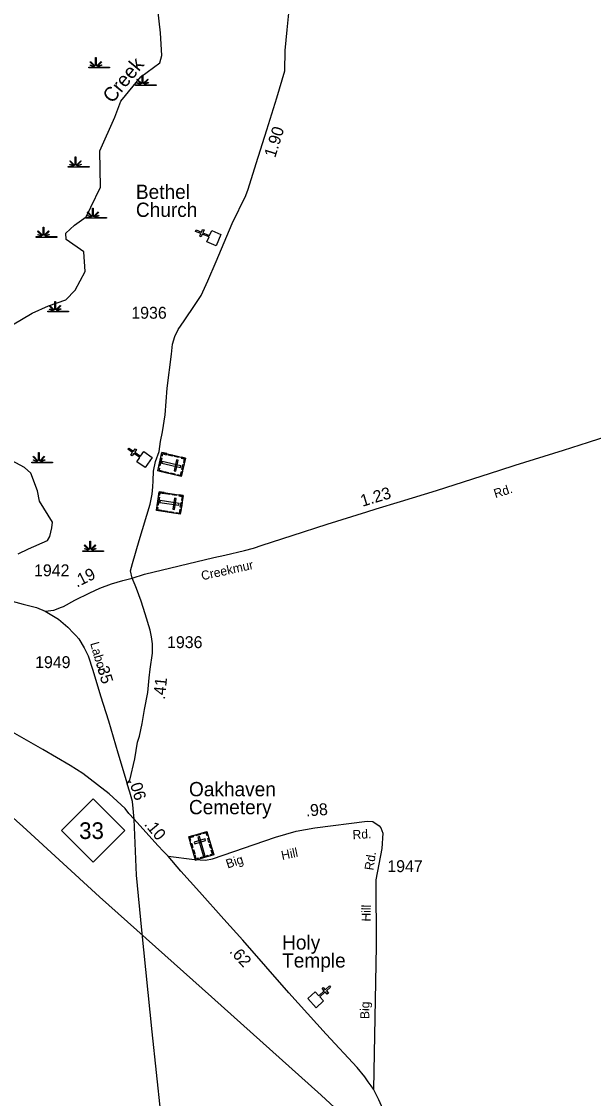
# Model space of a CAD drawing. Extents: x 2532689 to 2764727, y 536648 to 732970.
# Drawn here: x 2635202 to 2641218, y 574044 to 585362 of the extents above; entities that cross this region are included whole.
import ezdxf

# ---------------------------------------------------------------- set-up
doc = ezdxf.new("R2010")
doc.units = 0
for name, color, linetype in [('Exist Cultural Cemetery CELL', 7, 'Continuous'), ('Exist Cultural Cemetery Label', 7, 'Continuous'), ('Exist Cultural Church CELL', 7, 'Continuous'), ('Exist Cultural Church Label', 7, 'Continuous'), ('Exist Hydrographic Creek Single Shore', 7, 'Continuous'), ('Exist Hydrographic Creek Single Shore Label', 7, 'Continuous'), ('Exist Hydrographic Swamp CELL', 7, 'Continuous'), ('Exist Railroad Mainline', 7, 'Continuous'), ('Exist Road Primary Interstate Shield CELL', 7, 'Continuous'), ('Exist Road Primary NC Attributed', 7, 'Continuous'), ('Exist Road Primary NC Mileage Hundredths English Label', 7, 'Continuous'), ('Exist Road Primary NC Shield CELL', 7, 'Continuous'), ('Exist Road Primary NC Shield Number Label', 7, 'Continuous'), ('Exist Road Secondary Mileage Hundredths English Label', 7, 'Continuous'), ('Exist Road Secondary Type 20 Attributed', 7, 'Continuous'), ('Exist Road Secondary Type 51 Attributed', 7, 'Continuous'), ('Exist Road Secondary Type 51 Label', 7, 'Continuous'), ('Exist Road Secondary Type 51 Number Label', 7, 'Continuous')]:
    doc.layers.add(name, color=color, linetype=linetype)

# ---------------------------------------------------------------- blocks, each defined once
blk = doc.blocks.new('Exist Cultural Church')
at = {"layer": 'Exist Road Primary Interstate Shield CELL'}
blk.add_lwpolyline([(-65, 27), (-8, 27), (-8, 103), (-40, 103), (-40, 119), (-8, 119), (-8, 179), (8, 179), (8, 119), (40, 119), (40, 103), (8, 103), (8, 27), (65, 27), (65, -80), (-65, -80)], close=True, dxfattribs=at)

msp = doc.modelspace()

# ---------------------------------------------------------------- linework, layer by layer
at = {"layer": 'Exist Cultural Cemetery CELL'}
for points in [[(2636927, 580775), (2636882, 580581), (2636634, 580639), (2636679, 580833)], [(2636677, 580774), (2636658, 580692), (2636647, 580694), (2636666, 580777)], [(2636671, 580801), (2636683, 580798), (2636688, 580819), (2636727, 580810), (2636730, 580821), (2636679, 580833)], [(2636874, 580676), (2636878, 580694), (2636680, 580740), (2636676, 580722)], [(2636747, 580817), (2636789, 580807), (2636787, 580796), (2636744, 580806)], [(2636851, 580751), (2636833, 580755), (2636807, 580640), (2636825, 580636)], [(2636813, 580802), (2636855, 580792), (2636852, 580781), (2636810, 580791)], [(2636885, 580785), (2636882, 580774), (2636914, 580767), (2636904, 580727), (2636915, 580725), (2636927, 580775)], [(2636641, 580671), (2636653, 580669), (2636648, 580647), (2636687, 580638), (2636684, 580627), (2636634, 580639)], [(2636707, 580634), (2636749, 580624), (2636746, 580613), (2636704, 580623)], [(2636840, 580591), (2636842, 580602), (2636874, 580595), (2636883, 580634), (2636894, 580632), (2636882, 580581)], [(2636910, 580703), (2636898, 580653), (2636887, 580655), (2636899, 580706)], [(2636771, 580619), (2636813, 580609), (2636811, 580598), (2636768, 580608)], [(2636903, 580381), (2636872, 580184), (2636620, 580224), (2636651, 580421)], [(2636646, 580388), (2636657, 580386), (2636661, 580408), (2636701, 580402), (2636702, 580413), (2636651, 580421)], [(2636720, 580410), (2636763, 580403), (2636761, 580392), (2636718, 580398)], [(2636787, 580399), (2636829, 580392), (2636828, 580381), (2636785, 580388)], [(2636654, 580362), (2636640, 580278), (2636629, 580280), (2636642, 580364)], [(2636857, 580278), (2636860, 580296), (2636659, 580328), (2636656, 580309)], [(2636829, 580351), (2636811, 580354), (2636792, 580238), (2636811, 580235)], [(2636860, 580388), (2636858, 580376), (2636890, 580371), (2636884, 580331), (2636895, 580329), (2636903, 580381)], [(2636891, 580308), (2636883, 580256), (2636872, 580258), (2636880, 580309)], [(2636625, 580257), (2636637, 580255), (2636633, 580233), (2636673, 580227), (2636671, 580216), (2636620, 580224)], [(2636693, 580224), (2636736, 580217), (2636734, 580206), (2636691, 580213)], [(2636758, 580214), (2636801, 580207), (2636799, 580196), (2636756, 580202)], [(2636829, 580191), (2636830, 580202), (2636862, 580197), (2636869, 580237), (2636880, 580235), (2636871, 580184)], [(2636960, 576793), (2637151, 576850), (2637224, 576605), (2637033, 576549)], [(2636973, 576751), (2636983, 576754), (2636974, 576785), (2637013, 576797), (2637010, 576808), (2636960, 576793)], [(2637031, 576814), (2637081, 576829), (2637084, 576818), (2637034, 576803)], [(2637073, 576796), (2637055, 576790), (2637113, 576596), (2637131, 576601)], [(2637163, 576808), (2637153, 576805), (2637143, 576836), (2637105, 576824), (2637101, 576835), (2637151, 576849)], [(2637173, 576735), (2637161, 576776), (2637172, 576779), (2637184, 576738)], [(2636994, 576680), (2636981, 576722), (2636992, 576725), (2637005, 576683)], [(2637019, 576739), (2637024, 576721), (2637137, 576755), (2637132, 576773)], [(2637192, 576671), (2637180, 576713), (2637191, 576716), (2637203, 576675)], [(2637013, 576616), (2637000, 576657), (2637011, 576660), (2637024, 576619)], [(2637065, 576558), (2637061, 576569), (2637040, 576563), (2637029, 576602), (2637018, 576598), (2637033, 576549)], [(2637085, 576576), (2637166, 576600), (2637169, 576589), (2637088, 576565)], [(2637192, 576596), (2637189, 576607), (2637210, 576613), (2637198, 576652), (2637209, 576655), (2637224, 576605)]]:
    msp.add_lwpolyline(points, close=True, dxfattribs=at)
at = {"layer": 'Exist Cultural Church CELL'}
for points in [[(2637151, 583046), (2637174, 583098), (2637103, 583128), (2637091, 583098), (2637076, 583105), (2637089, 583134), (2637033, 583157), (2637040, 583172), (2637095, 583149), (2637107, 583178), (2637122, 583172), (2637110, 583143), (2637180, 583113), (2637202, 583166), (2637300, 583124), (2637250, 583004)], [(2636414, 580734), (2636446, 580781), (2636383, 580824), (2636365, 580797), (2636352, 580806), (2636370, 580833), (2636320, 580867), (2636329, 580880), (2636379, 580846), (2636397, 580873), (2636410, 580864), (2636392, 580837), (2636455, 580795), (2636487, 580842), (2636576, 580782), (2636502, 580674)]]:
    msp.add_lwpolyline(points, close=True, dxfattribs=at)
at = {"layer": 'Exist Hydrographic Creek Single Shore'}
for points in [[(2635671, 583072), (2635669, 583137), (2635759, 583223), (2635882, 583310), (2635930, 583411), (2636033, 583622), (2636025, 584005), (2636184, 584357), (2636247, 584527), (2636458, 584781), (2636655, 584927), (2636678, 585004), (2636664, 585243), (2636613, 585677)], [(2635107, 582176), (2635313, 582296), (2635486, 582375), (2635668, 582438), (2635766, 582540), (2635870, 582735), (2635857, 582941), (2635671, 583072)], [(2635168, 579768), (2635276, 579822), (2635474, 579909), (2635498, 579949), (2635521, 580042), (2635528, 580101), (2635390, 580322), (2635371, 580430), (2635300, 580614), (2635232, 580677), (2634962, 580820)]]:
    msp.add_lwpolyline(points, dxfattribs=at)
at = {"layer": 'Exist Hydrographic Swamp CELL'}
for points in [[(2635909, 584882), (2635962, 584882), (2635964, 584886), (2635926, 584901), (2635928, 584906), (2635966, 584890), (2635968, 584893), (2635923, 584937), (2635928, 584943), (2635974, 584897), (2635980, 584899), (2635980, 584983), (2635987, 584983), (2635987, 584899), (2635994, 584897), (2636039, 584943), (2636044, 584937), (2636000, 584893), (2636002, 584889), (2636043, 584908), (2636045, 584903), (2636004, 584885), (2636006, 584882), (2636127, 584882), (2636127, 584875), (2635909, 584875)], [(2636400, 584698), (2636453, 584698), (2636455, 584702), (2636416, 584716), (2636419, 584722), (2636457, 584706), (2636459, 584709), (2636414, 584753), (2636419, 584758), (2636465, 584713), (2636471, 584715), (2636471, 584798), (2636478, 584798), (2636478, 584715), (2636484, 584713), (2636530, 584758), (2636535, 584753), (2636491, 584709), (2636493, 584705), (2636533, 584724), (2636536, 584719), (2636495, 584701), (2636496, 584698), (2636618, 584698), (2636618, 584691), (2636400, 584691)], [(2635694, 583838), (2635747, 583838), (2635749, 583842), (2635711, 583857), (2635714, 583862), (2635751, 583846), (2635753, 583849), (2635709, 583894), (2635714, 583899), (2635759, 583853), (2635765, 583856), (2635765, 583939), (2635773, 583939), (2635773, 583856), (2635779, 583853), (2635824, 583899), (2635829, 583894), (2635785, 583849), (2635787, 583846), (2635828, 583864), (2635830, 583859), (2635789, 583841), (2635791, 583838), (2635912, 583838), (2635912, 583831), (2635694, 583831)], [(2635878, 583301), (2635931, 583301), (2635933, 583305), (2635895, 583320), (2635898, 583325), (2635935, 583309), (2635937, 583312), (2635893, 583356), (2635898, 583362), (2635943, 583316), (2635949, 583318), (2635949, 583402), (2635957, 583402), (2635957, 583318), (2635963, 583316), (2636008, 583362), (2636013, 583356), (2635969, 583312), (2635971, 583308), (2636012, 583327), (2636014, 583322), (2635973, 583304), (2635975, 583301), (2636096, 583301), (2636096, 583294), (2635878, 583294)], [(2635357, 583102), (2635410, 583102), (2635412, 583105), (2635373, 583120), (2635376, 583125), (2635414, 583109), (2635416, 583112), (2635371, 583157), (2635376, 583162), (2635422, 583117), (2635428, 583119), (2635428, 583202), (2635435, 583202), (2635435, 583119), (2635441, 583117), (2635487, 583162), (2635492, 583157), (2635447, 583112), (2635449, 583109), (2635490, 583127), (2635493, 583122), (2635452, 583105), (2635453, 583102), (2635574, 583102), (2635574, 583094), (2635357, 583094)], [(2635480, 582319), (2635532, 582319), (2635534, 582322), (2635496, 582337), (2635499, 582342), (2635537, 582327), (2635538, 582330), (2635494, 582374), (2635499, 582379), (2635544, 582334), (2635551, 582336), (2635551, 582419), (2635558, 582419), (2635558, 582336), (2635564, 582334), (2635609, 582379), (2635615, 582374), (2635570, 582330), (2635572, 582326), (2635613, 582345), (2635615, 582340), (2635574, 582322), (2635576, 582319), (2635697, 582319), (2635697, 582312), (2635480, 582312)], [(2635310, 580732), (2635363, 580733), (2635365, 580736), (2635326, 580751), (2635329, 580756), (2635367, 580740), (2635369, 580743), (2635324, 580788), (2635329, 580793), (2635375, 580747), (2635381, 580750), (2635381, 580833), (2635388, 580833), (2635388, 580750), (2635395, 580747), (2635440, 580793), (2635445, 580788), (2635401, 580743), (2635403, 580740), (2635443, 580758), (2635446, 580753), (2635405, 580735), (2635407, 580733), (2635528, 580732), (2635528, 580725), (2635310, 580725)], [(2635848, 579801), (2635900, 579801), (2635902, 579805), (2635864, 579820), (2635867, 579825), (2635905, 579809), (2635906, 579812), (2635862, 579857), (2635867, 579862), (2635912, 579816), (2635919, 579819), (2635919, 579902), (2635926, 579902), (2635926, 579819), (2635932, 579816), (2635978, 579862), (2635983, 579857), (2635938, 579812), (2635940, 579809), (2635981, 579827), (2635984, 579822), (2635943, 579804), (2635944, 579801), (2636065, 579801), (2636065, 579794), (2635848, 579794)]]:
    msp.add_lwpolyline(points, close=True, dxfattribs=at)
at = {"layer": 'Exist Railroad Mainline'}
msp.add_lwpolyline([(2623480, 582454), (2630987, 579432), (2631132, 579385), (2631273, 579334), (2631408, 579295), (2631458, 579280), (2633928, 578052), (2635217, 576901), (2636021, 576162), (2637199, 575112), (2638354, 574078), (2639181, 573315), (2639635, 572920), (2639933, 572574), (2640299, 572140), (2640552, 571834), (2640858, 571472), (2641178, 571089), (2641375, 570864)], dxfattribs=at)
at = {"layer": 'Exist Road Primary NC Attributed'}
for points in [[(2636385, 576981), (2636332, 577040), (2636292, 577091), (2636123, 577245), (2636002, 577340), (2635845, 577459), (2635712, 577543), (2635427, 577712), (2635084, 577907), (2634767, 578089)], [(2636746, 576590), (2636694, 576638), (2636637, 576704), (2636385, 576981)], [(2638906, 574142), (2638879, 574177), (2638848, 574220), (2638813, 574271), (2638733, 574368), (2638408, 574721), (2638014, 575154), (2637530, 575708), (2637330, 575928), (2637074, 576215), (2636877, 576433), (2636746, 576590)], [(2640314, 569721), (2640238, 569792), (2640156, 569865), (2640060, 569996), (2639996, 570116), (2639957, 570244), (2639932, 570350), (2639841, 570684), (2639635, 571493), (2639475, 572118), (2639462, 572170), (2639449, 572221), (2639432, 572279), (2639414, 572337), (2639385, 572480), (2639272, 572901), (2639058, 573761), (2639003, 573935), (2638962, 574030), (2638906, 574142)]]:
    msp.add_lwpolyline(points, dxfattribs=at)
at = {"layer": 'Exist Road Primary NC Shield CELL'}
msp.add_lwpolyline([(2635621, 576861), (2635954, 577194), (2636287, 576861), (2635954, 576528)], close=True, dxfattribs=at)
at = {"layer": 'Exist Road Secondary Type 20 Attributed'}
msp.add_lwpolyline([(2636365, 579512), (2636494, 579553), (2637226, 579728), (2637340, 579754), (2637547, 579804), (2637642, 579828), (2637733, 579858), (2638050, 579959), (2638417, 580078), (2638833, 580209), (2638933, 580240), (2639188, 580317), (2639567, 580435), (2640233, 580648), (2640395, 580700), (2640699, 580793), (2640904, 580858), (2641165, 580940), (2641395, 581014)], dxfattribs=at)
at = {"layer": 'Exist Road Secondary Type 51 Attributed'}
for points in [[(2636365, 579512), (2636347, 579588), (2636368, 579666), (2636441, 579907), (2636556, 580291), (2636575, 580396), (2636582, 580472), (2636585, 580534), (2636590, 580636), (2636610, 580740), (2636648, 580843), (2636665, 580949), (2636684, 581051), (2636712, 581230), (2636734, 581510), (2636779, 581868), (2636791, 581970), (2636814, 582052), (2636848, 582126), (2636914, 582217), (2637028, 582390), (2637092, 582484), (2637161, 582636), (2637251, 582839), (2637417, 583239), (2637562, 583534), (2637587, 583602), (2637671, 583872), (2637781, 584225), (2637886, 584559), (2637970, 584845), (2637976, 585057), (2637996, 585276), (2638016, 585484)], [(2634156, 579541), (2634265, 579490), (2634419, 579427), (2634592, 579377), (2634855, 579321), (2635050, 579283), (2635218, 579239), (2635360, 579204), (2635452, 579166)], [(2635452, 579166), (2635542, 579177), (2635623, 579206), (2635642, 579215), (2635761, 579280), (2635922, 579359), (2636027, 579406), (2636148, 579452), (2636268, 579489), (2636365, 579512)], [(2636313, 577349), (2636340, 577390), (2636393, 577614), (2636423, 577788), (2636444, 577850), (2636471, 577984), (2636494, 578131), (2636530, 578310), (2636545, 578466), (2636556, 578556), (2636579, 578723), (2636581, 578823), (2636570, 578897), (2636555, 578965), (2636501, 579138), (2636460, 579271), (2636412, 579404), (2636396, 579439), (2636365, 579512)], [(2635452, 579166), (2635589, 579081), (2635690, 578998), (2635750, 578933), (2635774, 578909), (2635805, 578876), (2635862, 578781), (2635902, 578697), (2635952, 578545), (2636034, 578275), (2636116, 578013), (2636214, 577675), (2636313, 577349)], [(2636385, 576981), (2636368, 577165), (2636340, 577264), (2636313, 577349)], [(2636667, 573888), (2636576, 574744), (2636469, 575812), (2636412, 576391), (2636385, 576981)], [(2636746, 576590), (2637023, 576554), (2637136, 576550), (2637211, 576563), (2637872, 576790), (2638090, 576853), (2638288, 576889), (2638837, 576957), (2638899, 576955), (2638963, 576910), (2638983, 576887)], [(2638983, 576887), (2639004, 576832), (2638993, 576672), (2638928, 576343), (2638931, 575644), (2638906, 574142)]]:
    msp.add_lwpolyline(points, dxfattribs=at)

# ---------------------------------------------------------------- block references
at = {"layer": 'Exist Cultural Church CELL', "rotation": -47.63063884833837}
msp.add_blockref('Exist Cultural Church', (2638315, 575100), dxfattribs=at)

# ---------------------------------------------------------------- texts
at = {"layer": 'Exist Cultural Cemetery Label'}
for s, p in [('Oakhaven', (2636963, 577220)), ('Cemetery', (2636963, 577031))]:
    msp.add_text(s, height=150, dxfattribs=at).set_placement(p)
at = {"layer": 'Exist Cultural Church Label'}
for s, p in [('Bethel', (2636405, 583498)), ('Church', (2636405, 583309)), ('Holy', (2637943, 575609)), ('Temple', (2637943, 575420))]:
    msp.add_text(s, height=150, dxfattribs=at).set_placement(p)
at = {"layer": 'Exist Hydrographic Creek Single Shore Label'}
msp.add_text('Creek', height=150, rotation=50.3695, dxfattribs=at).set_placement((2636157, 584495))
at = {"layer": 'Exist Road Primary NC Mileage Hundredths English Label'}
for s, rotation, p in [('.10', 309.8557, (2636486, 576923)), ('.62', 312.5985, (2637382, 575584))]:
    msp.add_text(s, height=125, rotation=rotation, dxfattribs=at).set_placement(p)
at = {"layer": 'Exist Road Primary NC Shield Number Label'}
msp.add_text('33', height=175, dxfattribs=at).set_placement((2635808, 576771))
at = {"layer": 'Exist Road Secondary Mileage Hundredths English Label'}
for s, rotation, p in [('1.90', 72.5898, (2637870, 583924)), ('1.23', 16.7365, (2638788, 580262)), ('.19', 26.2985, (2635784, 579412)), ('.35', 286.8321, (2635983, 578613)), ('.41', 84.2759, (2636710, 578232)), ('.06', 287.3413, (2636329, 577387)), ('.98', 4.3583, (2638196, 577007))]:
    msp.add_text(s, height=125, rotation=rotation, dxfattribs=at).set_placement(p)
at = {"layer": 'Exist Road Secondary Type 51 Label'}
for s, rotation, p in [('Rd.', 17.7632, (2640187, 580352)), ('Creekmur', 12.5882, (2637103, 579489)), ('Labor', 285.9813, (2635923, 578827)), ('Rd.', 3.5294, (2638687, 576768)), ('Hill', 11.9014, (2637944, 576550)), ('Big', 18.2386, (2637370, 576460)), ('Rd.', 81.5472, (2638903, 576437)), ('Hill', 89.1093, (2638874, 575903)), ('Big', 89.1093, (2638859, 574878))]:
    msp.add_text(s, height=95, rotation=rotation, dxfattribs=at).set_placement(p)
at = {"layer": 'Exist Road Secondary Type 51 Number Label'}
for s, p in [('1936', (2636357, 582239)), ('1942', (2635334, 579532)), ('1936', (2636733, 578777)), ('1949', (2635345, 578567)), ('1947', (2639050, 576423))]:
    msp.add_text(s, height=125, dxfattribs=at).set_placement(p)

doc.saveas('drawing.dxf')
